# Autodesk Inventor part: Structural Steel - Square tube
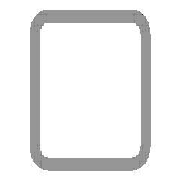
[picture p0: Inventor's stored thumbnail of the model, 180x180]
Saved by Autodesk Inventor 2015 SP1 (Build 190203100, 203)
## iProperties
_CCFamilyMember: 2
_CCFamilyDisplayName: ISO 4019 (Square) - Structural steels - Cold-formed, welded, structural hollow sections
_FrameMemberDoc: Frame Member File
_Version: 15.0.0
_GetPNFromCC: 1
Created: 2011-06
Part Number: Structural Steel - Square tube
Material: Stainless Steel
Document SubType Name: Modeling
Standard: ISO
Designer: Guilherme Augusto Franco de Souza
Standard Revision: Second edition 2001-09-01
Standards Organization: ISO
Language: en-US
Size Designation: 25x25x2
Categories: <MemberInstance><Categories><Category DisplayName="Structural Shapes" InternalName="089c4875-fa83-4c05-b084-43b9cc11f5ed" Mnemonic="GRDR"><CategoryParameter Dis
Stock Number: 25x25x2
Density: 8.08 g/cm^3
Description: ISO 4019 - 25x25x2
Appearance: Steel
G_L: 225,000 mm
G_W: 25,000 mm
G_H: 25,000 mm
+0BBAD034-F051-4CFB-B233-7F78D051060E+CUTDETAIL1: Miter 45,00 deg
+682B370D-6801-42C2-BA32-01057F22B1C2+CUTDETAIL2: Cut
IsCustomPart: 1
Author: Guilherme Augusto Franco de Souza
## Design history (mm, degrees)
node "Start plane"
node "End plane"
sketch "Sketch"
  geometry: L1 (-12.5, -8.5)-(-12.5, 8.5); L2 (-8.5, 12.5)-(8.5, 12.5); L3 (12.5, 8.5)-(12.5, -8.5); L4 (8.5, -12.5)-(-8.5, -12.5); L5 (-8.5, 10.5)-(8.5, 10.5); L6 (10.5, 8.5)-(10.5, -8.5); L7 (8.5, -10.5)-(-8.5, -10.5); L8 (-10.5, -8.5)-(-10.5, 8.5); L9 (0, 18.66)-(0, -18.66) reference; L10 (-18.66, 0)-(18.66, 0) reference; A1 r 4 centre (-8.5, -8.5) between (-12.5, -8.5) and (-8.5, -12.5); A2 r 4 centre (8.5, 8.5) between (12.5, 8.5) and (8.5, 12.5); A3 r 4 centre (-8.5, 8.5) between (-8.5, 12.5) and (-12.5, 8.5); A4 r 4 centre (8.5, -8.5) between (8.5, -12.5) and (12.5, -8.5); A5 r 2 centre (-8.5, 8.5) between (-8.5, 10.5) and (-10.5, 8.5); A6 r 2 centre (8.5, 8.5) between (10.5, 8.5) and (8.5, 10.5); A7 r 2 centre (8.5, -8.5) between (8.5, -10.5) and (10.5, -8.5); A8 r 2 centre (-8.5, -8.5) between (-10.5, -8.5) and (-8.5, -10.5)
  constraints: 16 end point, 16 point on circle, 8 centre point, 8 tangent, 4 parallel, 3 equal radius, 2 perpendicular, 7 other
  dimensions: "d7" = 4 radius of A1 (= G_IR); "d9" = 25 distance between parallel lines of L1 L3 (= G_W); "d11" = 25 distance between parallel lines of L2 L4 (= G_H); "d12" = 2 distance between parallel lines of L3 L6 (= G_T); "d15" = 12.5 distance between parallel lines of L9 L3 (= 0.5 x d9); "d16" = 12.5 distance between parallel lines of L2 L10 (= 0.5 x d11)
extrude "Body" new body sketch "Sketch" stored distance "d3" = 225 (= G_L); taper "d4" = 0 deg
node "Driven Length"
  sketch "Sketch3"
    geometry: L1 (0, 0)-(10, 0) reference
    constraints: 2 end point, 1 horizontal
  workplane "Work Plane3"
  sketch "Sketch4"
    geometry: L1 (-2, 0.141)-(12, 0.141) reference; L2 (-2, 200)-(12, 200) reference
    dimensions: "d18" = 199.85858 distance between parallel lines of L1 L2 (derived)
workplane "Work Plane4"
split "Split1"
workplane "Work Plane5"
split "Split2"
body "Solid1"
other parameters: "G_W" = 25 [user parameter; used in 1 equation term], "G_H" = 25 [user parameter; used in 1 equation term], "G_T" = 2 [user parameter; used in 1 equation term], "G_IR" = 4 [user parameter; used in 1 equation term], "G_L" = 225 [user parameter; used in 1 equation term], "G_OFFSET_START" = -0.14142 [user parameter; used in 1 equation term], "G_OFFSET_END" = -25 [user parameter; used in 1 equation term], "d13" = 0.14142 (= -G_OFFSET_START), "d14" = 200 (= G_OFFSET_END + B_L), "B_L" = 225 [user parameter; used in 1 equation term], "d17" = 90 deg, "MAS" = 0.136 [user parameter]
